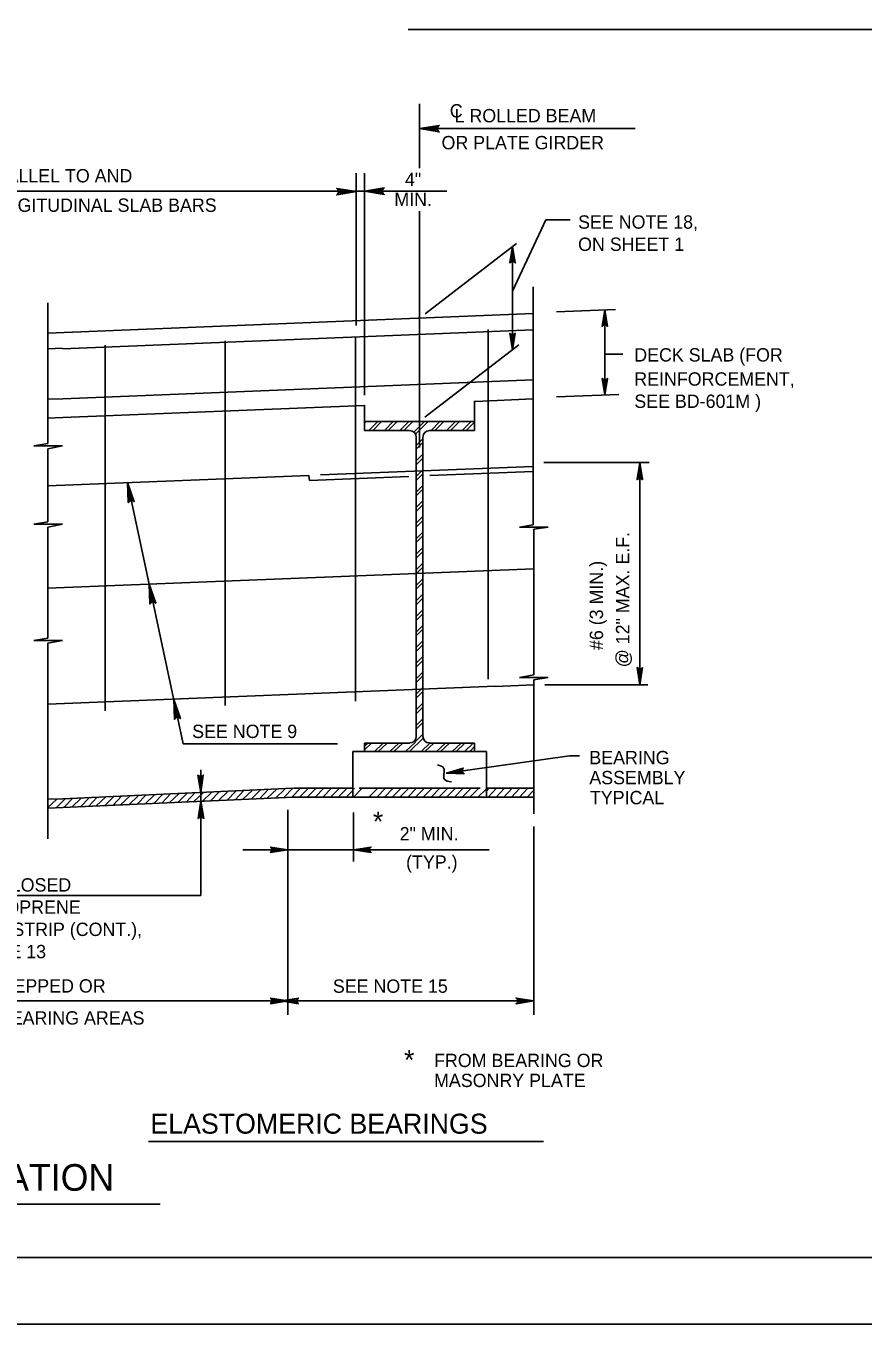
# Model space of a CAD drawing. Extents: x 640009 to 641706, y 298547 to 299735.
# Drawn here: x 640175.7 to 640364.1, y 298547.2 to 298839.2 of the extents above; entities that cross this region are included whole.
import ezdxf

# ---------------------------------------------------------------- set-up
doc = ezdxf.new("R2010")
doc.units = 0
doc.layers.add('1', color=7, linetype='Continuous')
doc.layers.add('PLT-BNDY', color=7, linetype='Continuous')

msp = doc.modelspace()

# ---------------------------------------------------------------- linework, layer by layer
at = {"layer": '1'}
for p, q in [((640261.67, 298838.4), (640460.34, 298838.4)), ((640264.23, 298807.27), (640264.23, 298821.73)), ((640264.23, 298816.13), (640312.77, 298816.13)), ((640249.98, 298806.12), (640249.98, 298771.87)), ((640251.86, 298806.12), (640251.86, 298756.17)), ((640078.94, 298802.06), (640270.39, 298802.06)), ((640264.23, 298744.36), (640264.23, 298797.57)), ((640285.21, 298779.56), (640292.7, 298795.61)), ((640292.7, 298795.61), (640298.16, 298795.61)), ((640265.5, 298774.44), (640286.1, 298790.31)), ((640285.21, 298766.39), (640285.21, 298789.62)), ((640289.86, 298727), (640289.86, 298780.5)), ((640180.61, 298745.27), (640180.61, 298776.9)), ((640295.05, 298774.9), (640308.33, 298775.43)), ((640305.98, 298756.21), (640305.98, 298775.34)), ((640180.61, 298770.12), (640289.86, 298774.5)), ((640183.86, 298766.62), (640289.86, 298770.87)), ((640249.86, 298769.37), (640249.86, 298687.28)), ((640279.73, 298692.25), (640279.73, 298770.95)), ((640180.61, 298766.62), (640183.86, 298766.75)), ((640193.48, 298767.42), (640193.48, 298685.12)), ((640220.48, 298768.37), (640220.48, 298686.37)), ((640265.48, 298751.21), (640286.61, 298767.48)), ((640305.98, 298765.4), (640310, 298765.4)), ((640183.98, 298755.37), (640289.86, 298759.62)), ((640180.61, 298755.24), (640183.98, 298755.37)), ((640276.61, 298754.87), (640276.61, 298748.25)), ((640276.82, 298754.77), (640289.86, 298755.37)), ((640295.05, 298755.77), (640309.09, 298756.34)), ((640183.98, 298751.12), (640251.89, 298753.84)), ((640251.86, 298753.92), (640251.86, 298748.25)), ((640180.61, 298750.99), (640183.98, 298751.12)), ((640264.23, 298750.25), (640251.86, 298750.25)), ((640264.23, 298750.25), (640251.86, 298750.25)), ((640251.86, 298750.25), (640251.86, 298749.25)), ((640264.23, 298750.25), (640251.86, 298750.25)), ((640251.86, 298750.25), (640251.86, 298748.25)), ((640264.23, 298750.25), (640276.61, 298750.25)), ((640264.23, 298750.25), (640276.61, 298750.25)), ((640264.23, 298750.25), (640276.61, 298750.25)), ((640276.61, 298750.25), (640276.61, 298749.25)), ((640276.61, 298750.25), (640276.61, 298748.25)), ((640261.98, 298748.25), (640251.86, 298748.25)), ((640261.98, 298748.25), (640251.86, 298748.25)), ((640263.48, 298746.75), (640263.48, 298713.12)), ((640263.48, 298746.75), (640263.48, 298713.12)), ((640264.98, 298746.75), (640264.98, 298713.12)), ((640264.98, 298746.75), (640264.98, 298713.12)), ((640266.48, 298748.25), (640276.61, 298748.25)), ((640266.48, 298748.25), (640276.61, 298748.25)), ((640177.48, 298744.77), (640180.61, 298745.27)), ((640177.48, 298744.77), (640183.86, 298744.77)), ((640180.61, 298744.12), (640183.86, 298744.77)), ((640180.61, 298735.8), (640180.61, 298744.12)), ((640180.73, 298744.77), (640180.73, 298744.77)), ((640241.98, 298738.25), (640289.86, 298740.12)), ((640292.23, 298741), (640315.98, 298741)), ((640313.86, 298741), (640313.86, 298691)), ((640180.61, 298735.8), (640239.36, 298738.12)), ((640239.48, 298737), (640239.36, 298738.12)), ((640239.48, 298737), (640261.86, 298737.87)), ((640266.61, 298738.12), (640289.86, 298739)), ((640180.61, 298727.63), (640180.61, 298735.8)), ((640198.5, 298736.51), (640211.04, 298677.68)), ((640177.48, 298727.13), (640180.61, 298727.63)), ((640177.48, 298727.13), (640183.86, 298727.13)), ((640180.61, 298726.48), (640183.86, 298727.13)), ((640180.61, 298701.5), (640180.61, 298726.48)), ((640180.73, 298727.13), (640180.73, 298727.13)), ((640286.73, 298726.5), (640289.86, 298727)), ((640286.73, 298726.5), (640293.23, 298726.5)), ((640289.98, 298726), (640293.23, 298726.5)), ((640289.98, 298726.5), (640289.98, 298726.5)), ((640289.98, 298693.25), (640289.98, 298726)), ((640180.61, 298712.77), (640289.98, 298717.12)), ((640263.48, 298679.37), (640263.48, 298713.12)), ((640263.48, 298679.37), (640263.48, 298713.12)), ((640264.98, 298679.37), (640264.98, 298713.12)), ((640264.98, 298679.37), (640264.98, 298713.12)), ((640177.48, 298701), (640180.61, 298701.5)), ((640177.48, 298701), (640183.86, 298701)), ((640180.61, 298700.35), (640183.86, 298701)), ((640180.61, 298656.37), (640180.61, 298700.35)), ((640180.73, 298701), (640180.73, 298701)), ((640286.73, 298692.62), (640289.98, 298693.25)), ((640180.61, 298686.62), (640281.35, 298690.69)), ((640281.36, 298690.62), (640289.98, 298691)), ((640286.73, 298692.62), (640293.23, 298692.62)), ((640289.98, 298692.12), (640293.23, 298692.62)), ((640289.98, 298662), (640289.98, 298692.12)), ((640292.48, 298691), (640315.61, 298691)), ((640211.04, 298677.68), (640245.78, 298677.68)), ((640249.23, 298665.75), (640249.23, 298676)), ((640249.23, 298676), (640279.36, 298676)), ((640261.98, 298677.87), (640251.86, 298677.87)), ((640251.86, 298676), (640251.86, 298677.87)), ((640261.98, 298677.87), (640251.86, 298677.87)), ((640251.86, 298676), (640251.86, 298677.87)), ((640279.36, 298676), (640251.86, 298676)), ((640264.23, 298676), (640251.86, 298676)), ((640264.23, 298676), (640276.61, 298676)), ((640266.48, 298677.87), (640276.61, 298677.87)), ((640266.48, 298677.87), (640276.61, 298677.87)), ((640276.61, 298676), (640276.61, 298677.87)), ((640276.61, 298676), (640276.61, 298677.87)), ((640279.36, 298665.75), (640279.36, 298676)), ((640297.98, 298675), (640270.3, 298671.08)), ((640297.98, 298675), (640300.23, 298675)), ((640215, 298671.89), (640215, 298643.6)), ((640235.73, 298667.75), (640183.98, 298665.37)), ((640235.86, 298667.75), (640249.23, 298667.75)), ((640277.91, 298667.75), (640250.7, 298667.75)), ((640279.36, 298667.75), (640289.86, 298667.75)), ((640183.86, 298665.37), (640180.61, 298665.23)), ((640235.86, 298665.75), (640183.98, 298663.37)), ((640235.86, 298665.75), (640249.23, 298665.75)), ((640249.23, 298665.75), (640279.23, 298665.75)), ((640279.36, 298665.75), (640289.86, 298665.75)), ((640183.98, 298663.37), (640180.61, 298663.22)), ((640234.61, 298662.87), (640234.61, 298616.74)), ((640249.36, 298662.25), (640249.36, 298651.25)), ((640289.98, 298659.12), (640289.98, 298616.74)), ((640224.48, 298653.87), (640252.11, 298653.87)), ((640249.11, 298653.87), (640279.96, 298653.87)), ((640141.96, 298643.6), (640215, 298643.6)), ((640112.98, 298619.87), (640234.61, 298619.87)), ((640234.61, 298619.87), (640289.98, 298619.87)), ((640203.25, 298588.21), (640292.13, 298588.21)), ((640146.11, 298574.16), (640205.89, 298574.16)), ((640835.47, 298562.17), (640049.47, 298562.17)), ((640835.47, 298562.17), (640049.47, 298562.17))]:
    msp.add_line(p, q, dxfattribs=at)
for points in [[(640268.48, 298815.59), (640268.3, 298815.91), (640264.23, 298816.13), (640268.48, 298815.59), (640268.69, 298815.41), (640264.23, 298816.13), (640268.3, 298816.33), (640268.46, 298816.63), (640264.23, 298816.13), (640268.69, 298816.85), (640268.46, 298816.63)], [(640245.82, 298801.42), (640245.99, 298801.74), (640250.06, 298801.96), (640245.82, 298801.42), (640245.61, 298801.23), (640250.06, 298801.96), (640245.99, 298802.16), (640245.84, 298802.46), (640250.06, 298801.96), (640245.61, 298802.68), (640245.84, 298802.46)], [(640256.1, 298802.6), (640255.93, 298802.29), (640251.86, 298802.06), (640256.1, 298802.6), (640256.31, 298802.79), (640251.86, 298802.06), (640255.93, 298801.86), (640256.08, 298801.56), (640251.86, 298802.06), (640256.31, 298801.34), (640256.08, 298801.56)], [(640285.66, 298786.08), (640285.39, 298786.23), (640285.21, 298789.62), (640285.66, 298786.08), (640285.81, 298785.91), (640285.21, 298789.62), (640285.04, 298786.23), (640284.79, 298786.1), (640285.21, 298789.62), (640284.6, 298785.91), (640284.79, 298786.1)], [(640306.43, 298771.8), (640306.17, 298771.95), (640305.98, 298775.34), (640306.43, 298771.8), (640306.58, 298771.63), (640305.98, 298775.34), (640305.82, 298771.95), (640305.56, 298771.82), (640305.98, 298775.34), (640305.38, 298771.63), (640305.56, 298771.82)], [(640285.66, 298769.93), (640285.39, 298769.79), (640285.21, 298766.39), (640285.66, 298769.93), (640285.81, 298770.11), (640285.21, 298766.39), (640285.04, 298769.79), (640284.79, 298769.92), (640285.21, 298766.39), (640284.6, 298770.11), (640284.79, 298769.92)], [(640306.43, 298759.75), (640306.17, 298759.6), (640305.98, 298756.21), (640306.43, 298759.75), (640306.58, 298759.92), (640305.98, 298756.21), (640305.82, 298759.6), (640305.56, 298759.73), (640305.98, 298756.21), (640305.38, 298759.92), (640305.56, 298759.73)], [(640251.86, 298749.87), (640252.23, 298750.25)], [(640252.86, 298748.25), (640254.86, 298750.25)], [(640253.73, 298748.25), (640255.73, 298750.25)], [(640256.36, 298748.25), (640258.36, 298750.25)], [(640257.23, 298748.25), (640259.23, 298750.25)], [(640259.86, 298748.25), (640261.86, 298750.25)], [(640260.73, 298748.25), (640262.73, 298750.25)], [(640262.98, 298747.87), (640265.36, 298750.25)], [(640263.36, 298747.37), (640266.23, 298750.25)], [(640266.86, 298748.25), (640268.86, 298750.25)], [(640267.73, 298748.25), (640269.73, 298750.25)], [(640270.36, 298748.25), (640272.36, 298750.25)], [(640271.23, 298748.25), (640273.23, 298750.25)], [(640273.86, 298748.25), (640275.86, 298750.25)], [(640274.73, 298748.25), (640276.61, 298750.12)], [(640263.48, 298744.87), (640264.98, 298746.37)], [(640276.48, 298748.25), (640276.61, 298748.37)], [(640263.48, 298744), (640264.98, 298745.5)], [(640263.48, 298741.37), (640264.98, 298742.87)], [(640263.48, 298740.5), (640264.98, 298742)], [(640313.36, 298737.25), (640313.73, 298737.37), (640313.86, 298741), (640313.36, 298737.25), (640313.23, 298737.12), (640313.86, 298741), (640314.11, 298737.37), (640314.36, 298737.25), (640313.86, 298741), (640314.48, 298737.12), (640314.36, 298737.25)], [(640314.29, 298737.42), (640314.03, 298737.57), (640313.84, 298740.96), (640314.29, 298737.42), (640314.45, 298737.25), (640313.84, 298740.96), (640313.68, 298737.57), (640313.43, 298737.44), (640313.84, 298740.96), (640313.24, 298737.25), (640313.43, 298737.44)], [(640263.48, 298737.87), (640264.98, 298739.37)], [(640263.48, 298737), (640264.98, 298738.5)], [(640198.87, 298732.19), (640199.06, 298732.38), (640198.5, 298736.51), (640198.87, 298732.19), (640198.69, 298732.01), (640198.5, 298736.51), (640199.44, 298732.57), (640199.81, 298732.38), (640198.5, 298736.51), (640200, 298732.19), (640199.81, 298732.38)], [(640263.48, 298734.37), (640264.98, 298735.87)], [(640263.48, 298733.5), (640264.98, 298735)], [(640263.48, 298730.87), (640264.98, 298732.37)], [(640263.48, 298730), (640264.98, 298731.5)], [(640263.48, 298727.37), (640264.98, 298728.87)], [(640263.48, 298726.5), (640264.98, 298728)], [(640263.48, 298723.87), (640264.98, 298725.37)], [(640263.48, 298723), (640264.98, 298724.5)], [(640263.48, 298720.37), (640264.98, 298721.87)], [(640263.48, 298719.5), (640264.98, 298721)], [(640263.48, 298716.87), (640264.98, 298718.37)], [(640263.48, 298716), (640264.98, 298717.5)], [(640203.75, 298709.33), (640203.93, 298709.52), (640203.37, 298713.64), (640203.75, 298709.33), (640203.56, 298709.14), (640203.37, 298713.64), (640204.31, 298709.71), (640204.68, 298709.52), (640203.37, 298713.64), (640204.87, 298709.33), (640204.68, 298709.52)], [(640263.48, 298713.37), (640264.98, 298714.87)], [(640263.48, 298712.5), (640264.98, 298714)], [(640263.48, 298709.87), (640264.98, 298711.37)], [(640263.48, 298709), (640264.98, 298710.5)], [(640263.48, 298706.37), (640264.98, 298707.87)], [(640263.48, 298705.5), (640264.98, 298707)], [(640263.48, 298702.87), (640264.98, 298704.37)], [(640263.48, 298702), (640264.98, 298703.5)], [(640263.48, 298699.37), (640264.98, 298700.87)], [(640263.48, 298698.5), (640264.98, 298700)], [(640263.48, 298695.87), (640264.98, 298697.37)], [(640263.48, 298695), (640264.98, 298696.5)], [(640263.48, 298692.37), (640264.98, 298693.87)], [(640263.48, 298691.5), (640264.98, 298693)], [(640314.36, 298694.75), (640314.11, 298694.62), (640313.86, 298691), (640314.36, 298694.75), (640314.48, 298694.87), (640313.86, 298691), (640313.73, 298694.62), (640313.48, 298694.75), (640313.86, 298691), (640313.23, 298694.87), (640313.48, 298694.75)], [(640263.48, 298688.87), (640264.98, 298690.37)], [(640209.3, 298683.41), (640209.49, 298683.6), (640208.93, 298687.72), (640209.3, 298683.41), (640209.11, 298683.22), (640208.93, 298687.72), (640209.86, 298683.79), (640210.24, 298683.6), (640208.93, 298687.72), (640210.43, 298683.41), (640210.24, 298683.6)], [(640263.48, 298688), (640264.98, 298689.5)], [(640263.48, 298685.37), (640264.98, 298686.87)], [(640263.48, 298684.5), (640264.98, 298686)], [(640263.48, 298681.87), (640264.98, 298683.37)], [(640263.48, 298681), (640264.98, 298682.5)], [(640261.98, 298676), (640265.11, 298679)], [(640263.36, 298678.25), (640264.98, 298679.87)], [(640251.86, 298676.37), (640253.48, 298677.87)], [(640251.86, 298677.25), (640252.61, 298677.87)], [(640254.11, 298676), (640256.11, 298677.87)], [(640254.98, 298676), (640256.98, 298677.87)], [(640257.61, 298676), (640259.61, 298677.87)], [(640258.48, 298676), (640260.48, 298677.87)], [(640261.11, 298676), (640263.36, 298678.12)], [(640264.61, 298676), (640266.61, 298677.87)], [(640265.48, 298676), (640267.48, 298677.87)], [(640268.11, 298676), (640270.11, 298677.87)], [(640268.98, 298676), (640270.98, 298677.87)], [(640271.61, 298676), (640273.61, 298677.87)], [(640272.48, 298676), (640274.48, 298677.87)], [(640274.36, 298676), (640276.36, 298677.87)], [(640275.61, 298676), (640276.61, 298677.12)], [(640215.46, 298670.55), (640215.21, 298670.42), (640215, 298666.8), (640215.46, 298670.55), (640215.58, 298670.68), (640215, 298666.8), (640214.83, 298670.42), (640214.58, 298670.54), (640215, 298666.8), (640214.33, 298670.66), (640214.58, 298670.54)], [(640274.05, 298671.13), (640273.94, 298671.39), (640270.3, 298671.08), (640274.05, 298671.13), (640274.3, 298670.99), (640270.3, 298671.08), (640273.84, 298671.77), (640273.98, 298672.13), (640270.3, 298671.08), (640274.11, 298672.25), (640273.98, 298672.13)], [(640211.73, 298664.62), (640213.73, 298666.75)], [(640213.48, 298664.75), (640215.61, 298666.75)], [(640215.36, 298664.75), (640217.48, 298666.87)], [(640217.23, 298664.87), (640219.23, 298667)], [(640218.98, 298665), (640221.11, 298667)], [(640220.86, 298665), (640222.98, 298667.12)], [(640222.73, 298665.12), (640224.73, 298667.25)], [(640224.48, 298665.25), (640226.61, 298667.25)], [(640226.36, 298665.25), (640228.48, 298667.37)], [(640228.23, 298665.37), (640230.23, 298667.5)], [(640229.98, 298665.5), (640232.11, 298667.5)], [(640231.86, 298665.5), (640233.98, 298667.62)], [(640233.73, 298665.62), (640235.73, 298667.75)], [(640235.48, 298665.75), (640237.48, 298667.75)], [(640237.23, 298665.75), (640239.23, 298667.75)], [(640238.98, 298665.75), (640240.98, 298667.75)], [(640240.73, 298665.75), (640242.73, 298667.75)], [(640242.48, 298665.75), (640244.48, 298667.75)], [(640244.23, 298665.75), (640246.23, 298667.75)], [(640245.98, 298665.75), (640247.98, 298667.75)], [(640247.73, 298665.75), (640249.23, 298667.25)], [(640249.23, 298667.37), (640249.61, 298667.75)], [(640249.36, 298665.75), (640251.36, 298667.75)], [(640252.86, 298665.75), (640254.86, 298667.75)], [(640254.61, 298665.75), (640256.61, 298667.75)], [(640256.36, 298665.75), (640258.36, 298667.75)], [(640258.11, 298665.75), (640260.11, 298667.75)], [(640259.86, 298665.75), (640261.86, 298667.75)], [(640261.61, 298665.75), (640263.61, 298667.75)], [(640263.36, 298665.75), (640265.36, 298667.75)], [(640265.11, 298665.75), (640267.11, 298667.75)], [(640266.86, 298665.75), (640268.86, 298667.75)], [(640268.61, 298665.75), (640270.61, 298667.75)], [(640270.36, 298665.75), (640272.36, 298667.75)], [(640272.11, 298665.75), (640274.11, 298667.75)], [(640273.86, 298665.75), (640275.86, 298667.75)], [(640275.61, 298665.75), (640277.61, 298667.75)], [(640277.36, 298665.75), (640279.23, 298667.5)], [(640279.36, 298667.12), (640279.86, 298667.75)], [(640279.73, 298665.75), (640281.61, 298667.75)], [(640281.48, 298665.75), (640283.36, 298667.75)], [(640283.23, 298665.75), (640285.11, 298667.75)], [(640284.98, 298665.75), (640286.86, 298667.75)], [(640286.73, 298665.75), (640288.61, 298667.75)], [(640288.48, 298665.75), (640289.86, 298667.12)], [(640180.61, 298663.37), (640182.61, 298665.25)], [(640180.61, 298665.11), (640180.73, 298665.25)], [(640182.36, 298663.25), (640184.48, 298665.37)], [(640184.23, 298663.37), (640186.23, 298665.5)], [(640185.98, 298663.5), (640188.11, 298665.5)], [(640187.86, 298663.5), (640189.98, 298665.62)], [(640189.73, 298663.62), (640191.73, 298665.75)], [(640191.48, 298663.75), (640193.61, 298665.75)], [(640193.36, 298663.75), (640195.48, 298665.87)], [(640195.23, 298663.87), (640197.23, 298666)], [(640196.98, 298664), (640199.11, 298666)], [(640198.86, 298664), (640200.98, 298666.12)], [(640200.73, 298664.12), (640202.73, 298666.25)], [(640202.48, 298664.25), (640204.61, 298666.25)], [(640204.36, 298664.25), (640206.48, 298666.37)], [(640206.23, 298664.37), (640208.23, 298666.5)], [(640207.98, 298664.5), (640210.11, 298666.5)], [(640209.86, 298664.5), (640211.98, 298666.62)], [(640214.58, 298661.03), (640214.82, 298661.16), (640215, 298664.79), (640214.58, 298661.03), (640214.45, 298660.91), (640215, 298664.79), (640215.2, 298661.17), (640215.45, 298661.05), (640215, 298664.79), (640215.7, 298660.93), (640215.45, 298661.05)], [(640279.11, 298665.75), (640279.23, 298665.75)], [(640230.86, 298654.37), (640230.98, 298654.12), (640234.61, 298653.87), (640230.86, 298654.37), (640230.73, 298654.5), (640234.61, 298653.87), (640230.98, 298653.75), (640230.86, 298653.5), (640234.61, 298653.87), (640230.73, 298653.25), (640230.86, 298653.5)], [(640253.11, 298653.5), (640252.98, 298653.75), (640249.36, 298653.87), (640253.11, 298653.5), (640253.36, 298653.25), (640249.36, 298653.87), (640252.98, 298654.12), (640253.11, 298654.37), (640249.36, 298653.87), (640253.36, 298654.5), (640253.11, 298654.37)], [(640230.86, 298620.37), (640230.98, 298620.12), (640234.61, 298619.87), (640230.86, 298620.37), (640230.73, 298620.5), (640234.61, 298619.87), (640230.98, 298619.75), (640230.86, 298619.5), (640234.61, 298619.87), (640230.73, 298619.25), (640230.86, 298619.5)], [(640236.86, 298619.37), (640236.73, 298619.62), (640233.11, 298619.87), (640236.86, 298619.37), (640236.98, 298619.25), (640233.11, 298619.87), (640236.61, 298620), (640236.86, 298620.37), (640233.11, 298619.87), (640236.98, 298620.5), (640236.86, 298620.37)], [(640286.23, 298620.37), (640286.36, 298620.12), (640289.98, 298619.87), (640286.23, 298620.37), (640285.98, 298620.5), (640289.98, 298619.87), (640286.36, 298619.75), (640286.23, 298619.37), (640289.98, 298619.87), (640285.98, 298619.25), (640286.23, 298619.37)]]:
    msp.add_lwpolyline(points, dxfattribs=at)
for centre, start, end in [((640262.04, 298746.72), 0, 90), ((640262.04, 298746.72), 0, 90), ((640266.49, 298746.72), 90, 180), ((640266.49, 298746.72), 90, 180), ((640262.04, 298679.4), 270, 0), ((640262.04, 298679.4), 270, 0), ((640266.49, 298679.4), 180, 270), ((640266.49, 298679.4), 180, 270)]:
    msp.add_arc(centre, 1.49, start, end, dxfattribs=at)
msp.add_spline([(640268.34, 298672.98), (640269.69, 298672.26), (640269.82, 298669.77), (640271.45, 298669.13)], degree=3, dxfattribs=at)
at = {"layer": 'PLT-BNDY'}
msp.add_lwpolyline([(640009.47, 299141.17), (640850.47, 299141.17), (640850.47, 298547.17), (640009.47, 298547.17)], close=True, dxfattribs=at)

# ---------------------------------------------------------------- texts
at = {"layer": '1'}
for s, height, p in [('C', 3, (640271.07, 298818.64)), ('L ROLLED BEAM', 3, (640272.14, 298817.55)), ('OR PLATE GIRDER', 3, (640269.21, 298811.48)), ('#4 @ 9" PLACED PARALLEL TO AND', 3, (640130.35, 298804.04)), ('4"', 3, (640260.98, 298803.2)), ('MIN.', 3, (640258.59, 298798.71)), ('CENTERED BETWEEN TOP LONGITUDINAL SLAB BARS', 3, (640112.04, 298797.41)), ('SEE NOTE 18,', 3, (640299.95, 298793.62)), ('ON SHEET 1', 3, (640299.95, 298788.62)), ('DECK SLAB (FOR', 3, (640312.59, 298763.73)), ('REINFORCEMENT, ', 3, (640312.6, 298758.3)), ('SEE BD-601M )', 3, (640312.6, 298753.3)), ('SEE NOTE 9', 3, (640213.08, 298679.02)), ('BEARING', 3, (640302.48, 298673.12)), ('ASSEMBLY', 3, (640302.48, 298668.62)), ('TYPICAL', 3, (640302.61, 298664.12)), ('*', 4.46, (640253.76, 298658.02)), ('2" MIN.', 3, (640259.79, 298655.98)), ('(TYP.)', 3, (640261.23, 298649.62)), ('1" THK. CLOSED', 3, (640154.33, 298644.48)), ('CELL NEOPRENE', 3, (640154.33, 298639.48)), ('SPONGE STRIP (CONT.),', 3, (640154.33, 298634.48)), ('SEE NOTE 13', 3, (640154.33, 298629.48)), ('BRIDGE SEAT-STEPPED OR', 3, (640139.43, 298621.75)), ('SEE NOTE 15', 3, (640244.75, 298621.7)), ('SLOPED BETWEEN BEARING AREAS', 3, (640131.23, 298614.55)), ('*', 4.46, (640260.78, 298604.37)), ('FROM BEARING OR', 3, (640267.53, 298604.99)), ('MASONRY PLATE', 3, (640267.53, 298600.49)), ('ELASTOMERIC BEARINGS', 4.5, (640203.68, 298590)), ('ELEVATION', 6, (640150.49, 298577.16))]:
    msp.add_text(s, height=height, dxfattribs=at).set_placement(p)
for s, p in [('@ 12" MAX. E.F.', (640311.47, 298694.93)), ('#6 (3 MIN.)', (640305.57, 298698.82))]:
    msp.add_text(s, height=3, rotation=90, dxfattribs=at).set_placement(p)

doc.saveas('drawing.dxf')
